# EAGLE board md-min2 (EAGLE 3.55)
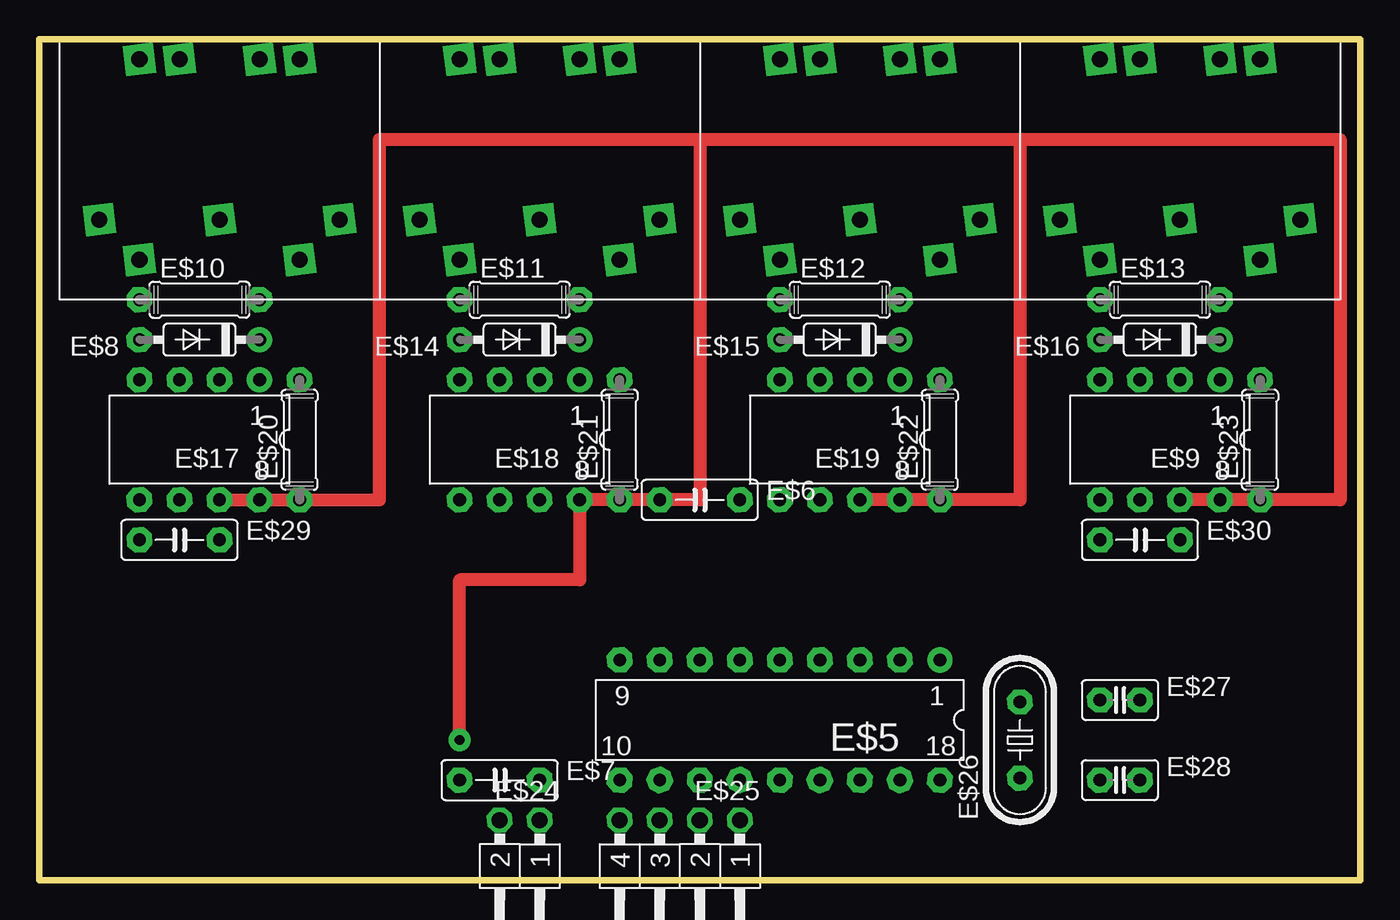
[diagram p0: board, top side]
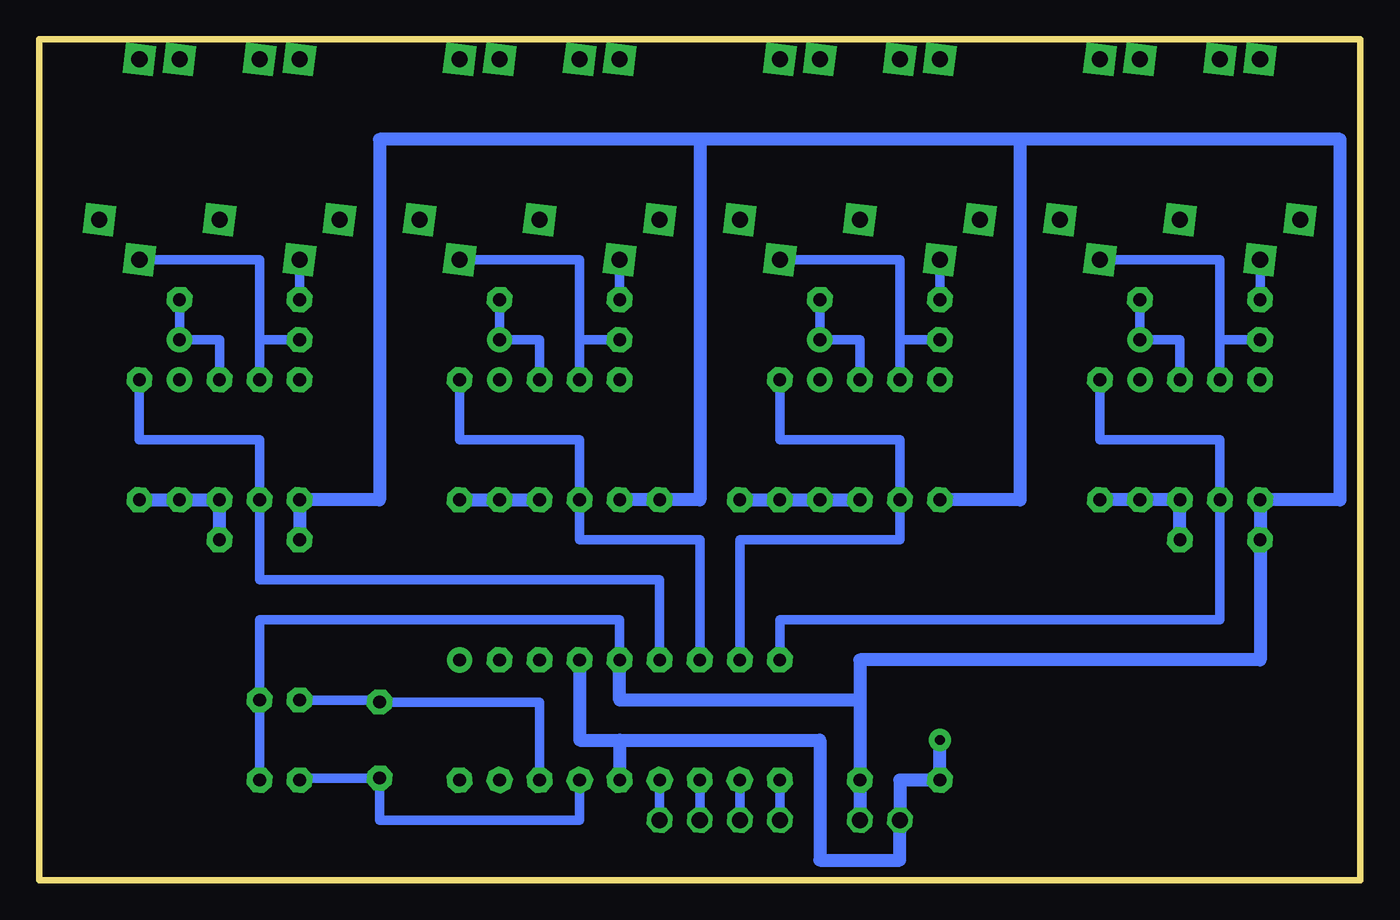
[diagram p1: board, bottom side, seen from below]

Size 83.82 x 53.34 mm. Coordinates in mm from the lower left corner, seen from the top.
Outline: 0,0 83.82,0 83.82,53.34 0,53.34 0,0
Copper layers used: Top, Bottom

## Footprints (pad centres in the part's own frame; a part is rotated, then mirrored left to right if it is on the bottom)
_PCB = drill 1.016 pad 1.93 square:  -7.62,10.16;  -5.08,10.16;  0,10.16;  2.54,10.16;  -2.54,0;  -7.62,-2.54;  -10.16,0;  2.54,-2.54;  5.08,0
L18 = drill 0.813 pad 1.6 round:  -10.16,-3.81 | drill 0.813 pad 1.6 octagon:  -7.62,-3.81;  -5.08,-3.81;  -2.54,-3.81;  0,-3.81;  2.54,-3.81;  5.08,-3.81;  7.62,-3.81;  10.16,-3.81;  10.16,3.81;  7.62,3.81;  5.08,3.81;  2.54,3.81;  0,3.81;  -2.54,3.81;  -5.08,3.81;  -7.62,3.81;  -10.16,3.81
B2,5 = drill 0.813 pad 1.6 octagon:  -2.54,0;  2.54,0
35-7 = drill 0.813 pad 1.6 round:  -3.81,0 | drill 0.813 pad 1.6 octagon:  3.81,0
L08 = drill 0.813 pad 1.6 round:  -3.81,-3.81 | drill 0.813 pad 1.6 octagon:  -1.27,-3.81;  1.27,-3.81;  3.81,-3.81;  3.81,3.81;  1.27,3.81;  -1.27,3.81;  -3.81,3.81
07/7 = drill 0.813 pad 1.6 octagon:  -3.81,0;  3.81,0
02-1W = drill 1.016 pad 1.6 octagon:  2.54,0;  0,0
04-1W = drill 1.016 pad 1.6 octagon:  7.62,0;  5.08,0;  2.54,0;  0,0
49/S = drill 0.813 pad 1.6 octagon:  -2.413,0;  2.413,0
,5-2 = drill 0.813 pad 1.6 octagon:  -1.27,0;  1.27,0

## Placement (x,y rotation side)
E$1  [_PCB]  13.97,41.91 0 top
E$2  [_PCB]  34.29,41.91 0 top
E$3  [_PCB]  54.61,41.91 0 top
E$4  [_PCB]  74.93,41.91 0 top
E$5  PIC16F84/10MHz  [L18]  46.99,10.16 180 top
E$6  0.1  [B2,5]  41.91,24.13 0 top
E$7  0.1  [B2,5]  29.21,6.35 0 top
E$8  1N4148  [35-7]  10.16,34.29 180 top
E$9  6N137  [L08]  71.12,27.94 180 top
E$10  220  [07/7]  10.16,36.83 0 top
E$11  220  [07/7]  30.48,36.83 0 top
E$12  220  [07/7]  50.8,36.83 0 top
E$13  220  [07/7]  71.12,36.83 0 top
E$14  1N4148  [35-7]  30.48,34.29 180 top
E$15  1N4148  [35-7]  50.8,34.29 180 top
E$16  1N4148  [35-7]  71.12,34.29 180 top
E$17  6N137  [L08]  10.16,27.94 180 top
E$18  6N137  [L08]  30.48,27.94 180 top
E$19  6N137  [L08]  50.8,27.94 180 top
E$20  360  [07/7]  16.51,27.94 90 top
E$21  360  [07/7]  36.83,27.94 90 top
E$22  360  [07/7]  57.15,27.94 90 top
E$23  360  [07/7]  77.47,27.94 90 top
E$24  [02-1W]  31.75,3.81 180 top
E$25  [04-1W]  44.45,3.81 180 top
E$26  10MHz  [49/S]  62.23,8.89 90 top
E$27  33p  [,5-2]  68.58,11.43 0 top
E$28  33p  [,5-2]  68.58,6.35 0 top
E$29  0.1  [B2,5]  8.89,21.59 0 top
E$30  0.1  [B2,5]  69.85,21.59 0 top

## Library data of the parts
E$1-E$4 = con-din
E$5 = PIC
E$6 E$7 E$27-E$30 = cap
E$8 E$14-E$16 = diode
E$9 E$17-E$19 = optocpl
E$10-E$13 E$20-E$23 = r
E$24 E$25 = con-lstb
E$26 = QUARTZ

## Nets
GND: E$5. E$6. E$7. E$9. E$17. E$18. E$19. E$24. E$27. E$28. E$29. E$30.
S$1: E$5. E$25.
S$2: E$2. E$11.
S$3: E$5. E$25.
S$4: E$1. E$10.
S$5: E$3. E$12.
S$6: E$4. E$13.
S$7: E$1. E$8. E$17.
S$8: E$8. E$10. E$17.
S$9: E$11. E$14. E$18.
S$10: E$12. E$15. E$19.
S$11: E$9. E$13. E$16.
S$12: E$4. E$9. E$16.
S$13: E$3. E$15. E$19.
S$14: E$2. E$14. E$18.
S$15: E$5. E$18. E$21.
S$16: E$5. E$19. E$22.
S$17: E$5. E$9. E$23.
S$18: E$5. E$17. E$20.
S$19: E$5. E$25.
S$20: E$5. E$25.
S$22: E$5. E$26. E$28.
S$23: E$5. E$26. E$27.
VCC: E$5. E$6. E$7. E$9. E$17. E$18. E$19. E$20. E$21. E$22. E$23. E$24. E$29. E$30.

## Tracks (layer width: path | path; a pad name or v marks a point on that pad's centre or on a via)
GND
  Bottom 0.61: E$28. E$27. 69.85,16.51 46.99,16.51 46.99,13.97
  Bottom 0.813: 67.31,21.59 67.31,24.13 62.23,24.13 62.23,46.99 41.91,46.99 | 46.99,24.13 E$6. 41.91,24.13 41.91,46.99 | 26.67,24.13 21.59,24.13 21.59,46.99 | 21.59,46.99 41.91,46.99 | 21.59,46.99 1.27,46.99 1.27,24.13 6.35,24.13 6.35,21.59 6.35,13.97 31.75,13.97 31.75,11.43 | 46.99,13.97 46.99,11.43 31.75,11.43 | E$24. E$7. 31.75,11.43
S$1
  Bottom 0.61: 36.83,6.35 36.83,3.81
S$2
  Bottom 0.61: 26.67,39.37 26.67,36.83
S$3
  Bottom 0.61: 39.37,6.35 39.37,3.81
S$4
  Bottom 0.61: 6.35,39.37 6.35,36.83
S$5
  Bottom 0.61: 46.99,39.37 46.99,36.83
S$6
  Bottom 0.61: 67.31,39.37 67.31,36.83
S$7
  Bottom 0.61: 8.89,31.75 8.89,34.29 | 8.89,34.29 E$8. | 8.89,34.29 8.89,39.37 16.51,39.37
S$8
  Bottom 0.61: E$10. 13.97,34.29 11.43,34.29 11.43,31.75
S$9
  Bottom 0.61: 31.75,31.75 31.75,34.29 34.29,34.29 E$11.
S$10
  Bottom 0.61: E$12. 54.61,34.29 52.07,34.29 52.07,31.75
S$11
  Bottom 0.61: E$13. 74.93,34.29 72.39,34.29 72.39,31.75
S$12
  Bottom 0.61: E$16. 69.85,34.29 | 69.85,34.29 69.85,31.75 | 69.85,34.29 69.85,39.37 77.47,39.37
S$13
  Bottom 0.61: 57.15,39.37 49.53,39.37 49.53,34.29 | 49.53,34.29 49.53,31.75 | 49.53,34.29 E$15.
S$14
  Bottom 0.61: 36.83,39.37 29.21,39.37 29.21,34.29 | 29.21,34.29 29.21,31.75 | E$14. 29.21,34.29
S$15
  Bottom 0.61: E$21. 36.83,27.94 29.21,27.94 29.21,24.13 29.21,21.59 39.37,21.59 39.37,13.97
S$16
  Bottom 0.61: E$22. 57.15,27.94 49.53,27.94 49.53,24.13 49.53,21.59 41.91,21.59 41.91,13.97
S$17
  Bottom 0.61: E$23. 77.47,27.94 69.85,27.94 69.85,24.13 69.85,19.05 44.45,19.05 44.45,13.97
S$18
  Bottom 0.61: E$20. 16.51,27.94 8.89,27.94 8.89,24.13 8.89,16.51 36.83,16.51 36.83,13.97
S$19
  Bottom 0.61: 41.91,6.35 41.91,3.81
S$20
  Bottom 0.61: E$25. 44.45,6.35
S$22
  Bottom 0.406: 67.31,6.48 67.31,6.35
  Bottom 0.61: 49.53,6.35 49.53,3.81 62.23,3.81 62.23,6.48 67.31,6.48
S$23
  Bottom 0.406: 62.23,11.43 E$26.
  Bottom 0.61: 67.31,11.43 62.23,11.43 | E$26. 52.07,11.3 52.07,6.35
VCC  (via drill 0.61 pad 1.42)
  Top 0.813: 72.39,24.13 E$9. 77.47,24.13 82.55,24.13 82.55,46.99 62.23,46.99 | 52.07,24.13 E$19. 57.15,24.13 62.23,24.13 62.23,46.99 | 41.91,46.99 41.91,24.13 39.37,24.13 36.83,24.13 E$18. 34.29,19.05 26.67,19.05 v26.67,8.89 | 41.91,46.99 62.23,46.99 | 41.91,46.99 21.59,46.99 21.59,24.13 16.51,24.13 E$17. 11.43,24.13
  Bottom 0.813: 31.75,24.13 E$18. 36.83,24.13 39.37,24.13 | 77.47,24.13 E$9. 72.39,24.13 E$30. | 52.07,24.13 E$19. 57.15,24.13 | 16.51,24.13 E$17. 11.43,24.13 E$29. | v26.67,8.89 26.67,6.35 29.21,6.35 29.21,3.81 29.21,1.27 34.29,1.27 34.29,8.89 46.99,8.89 | 49.53,13.97 49.53,8.89 46.99,8.89 | 46.99,8.89 46.99,6.35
